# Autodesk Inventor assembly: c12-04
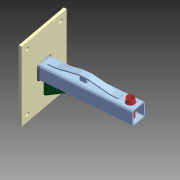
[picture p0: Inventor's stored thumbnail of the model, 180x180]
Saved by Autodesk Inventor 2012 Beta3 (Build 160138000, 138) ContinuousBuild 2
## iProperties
Created: 2011-01
Part Number: c12-04
Document SubType Name: Weldment
Designer: Beta-8540w
Weld Material: Welded Steel Mild
_SolveAssemblyDoc: Frame Generator Solve Assembly
_Version: 15.0.0
Author: Beta-8540w
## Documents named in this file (5)
- C:\Inventor 2012 Essentials\Assemblies\Chapter 12\c12-04.iam
- C:\Inventor 2012 Essentials\Parts\Chapter 12\c12-01.ipt
- C:\Inventor 2012 Essentials\Parts\Chapter 12\c12-02.ipt
- C:\Inventor 2012 Essentials\Assemblies\Chapter 12\Frame\Frame c12-01.iam
- C:\Inventor 2012 Essentials\Parts\Chapter 12\c12-03.ipt
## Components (4 placed, 4 different names)
1. c12-01:1 — Mate:2
2. c12-02:1 — Flush:1
3. Frame c12-01:1 [sub-assembly] — Mate:3
4. c12-03:1 — Mate:1, Mate:2, Mate:3
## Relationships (4: Mate 3, Flush 1)
- Flush:1: c12-02:1
- Mate:1: c12-03:1
- Mate:2: c12-01:1 ↔ c12-03:1
- Mate:3: Frame c12-01:1 ↔ c12-03:1
